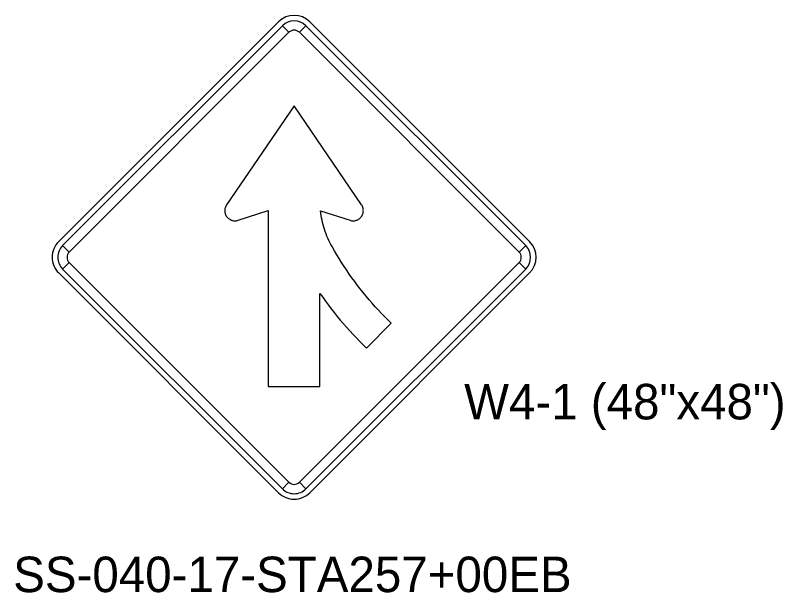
# Model space of a CAD drawing. Extents: x 620856.8 to 620948.6, y 415598.8 to 415658.2.
# Drawn here: x 620915.06 to 620923.7, y 415604 to 415610.5 of the extents above; entities that cross this region are included whole.
import ezdxf

# ---------------------------------------------------------------- set-up
doc = ezdxf.new("R2010")
doc.units = 0
doc.layers.add('SIGNS', color=7, linetype='Continuous')

msp = doc.modelspace()

# ---------------------------------------------------------------- linework, layer by layer
at = {"layer": 'SIGNS'}
for p, q in [((620918.0241, 415610.424), (620915.5492, 415607.9491)), ((620918.0683, 415610.3798), (620918.1419, 415610.3061)), ((620918.2598, 415610.3061), (620918.3334, 415610.3798)), ((620920.8525, 415607.9491), (620918.3776, 415610.424)), ((620917.4389, 415608.3624), (620917.4344, 415608.3546)), ((620917.5685, 415608.1889), (620917.908, 415608.298)), ((620917.908, 415608.298), (620917.908, 415606.3159)), ((620918.5006, 415608.2693), (620918.4974, 415608.2959)), ((620918.4974, 415608.2959), (620918.8304, 415608.1889)), ((620915.667, 415607.8312), (620915.5934, 415607.9049)), ((620920.8083, 415607.9049), (620920.7346, 415607.8312)), ((620915.5934, 415607.6397), (620915.667, 415607.7134)), ((620920.7346, 415607.7134), (620920.8083, 415607.6397)), ((620915.5492, 415607.5955), (620918.0241, 415605.1207)), ((620918.3776, 415605.1207), (620920.8525, 415607.5955)), ((620918.4908, 415606.3159), (620918.4908, 415607.3662)), ((620918.4908, 415607.3662), (620918.522, 415607.3219)), ((620919.0153, 415606.749), (620919.295, 415607.0287)), ((620917.908, 415606.3159), (620918.4908, 415606.3159)), ((620918.1419, 415605.2385), (620918.0683, 415605.1649)), ((620918.3334, 415605.1649), (620918.2598, 415605.2385))]:
    msp.add_line(p, q, dxfattribs=at)
for points in [[(620918.0683, 415610.3798), (620915.5934, 415607.9049), (620915.667, 415607.8312), (620918.1419, 415610.3061), (620918.0683, 415610.3798), (620918.0683, 415610.3798)], [(620920.8083, 415607.9049), (620918.3334, 415610.3798), (620918.2598, 415610.3061), (620920.7346, 415607.8312), (620920.8083, 415607.9049), (620920.8083, 415607.9049)], [(620915.5934, 415607.6397), (620918.0683, 415605.1649), (620918.1419, 415605.2385), (620915.667, 415607.7134), (620915.5934, 415607.6397), (620915.5934, 415607.6397)], [(620918.3334, 415605.1649), (620920.8083, 415607.6397), (620920.7346, 415607.7134), (620918.2598, 415605.2385), (620918.3334, 415605.1649), (620918.3334, 415605.1649)]]:
    msp.add_lwpolyline(points, close=True, dxfattribs=at)
for points in [[(620918.96, 415608.3624), (620918.1996, 415609.4787), (620917.4389, 415608.3624)], [(620917.4344, 415608.3546), (620917.4303, 415608.3468), (620917.4266, 415608.3386), (620917.4237, 415608.3304), (620917.4216, 415608.3218), (620917.42, 415608.3132), (620917.4192, 415608.3041), (620917.4192, 415608.2955), (620917.4196, 415608.2865), (620917.4208, 415608.2779), (620917.4229, 415608.2693), (620917.4253, 415608.2607), (620917.4286, 415608.2525), (620917.4323, 415608.2443), (620917.4368, 415608.2365), (620917.4417, 415608.2295), (620917.4475, 415608.2225), (620917.4536, 415608.216), (620917.4602, 415608.2102), (620917.4672, 415608.2045), (620917.4746, 415608.2), (620917.4823, 415608.1955), (620917.4905, 415608.1918), (620917.4987, 415608.1889), (620917.5074, 415608.1864), (620917.516, 415608.1848), (620917.5246, 415608.1836), (620917.5336, 415608.1836), (620917.5426, 415608.184), (620917.5512, 415608.1848), (620917.5599, 415608.1864), (620917.5685, 415608.1889)], [(620918.8304, 415608.1889), (620918.839, 415608.1864), (620918.8476, 415608.1848), (620918.8566, 415608.184), (620918.8656, 415608.1836), (620918.8742, 415608.1836), (620918.8833, 415608.1848), (620918.8919, 415608.1864), (620918.9005, 415608.1889), (620918.9087, 415608.1918), (620918.9169, 415608.1955), (620918.9247, 415608.2), (620918.9321, 415608.2045), (620918.939, 415608.2102), (620918.9456, 415608.216), (620918.9517, 415608.2225), (620918.9571, 415608.2295), (620918.9624, 415608.2365), (620918.9665, 415608.2443), (620918.9706, 415608.2525), (620918.9739, 415608.2607), (620918.9764, 415608.2693), (620918.978, 415608.2779), (620918.9792, 415608.2865), (620918.98, 415608.2955), (620918.9796, 415608.3041), (620918.9788, 415608.3132), (620918.9776, 415608.3218), (620918.9751, 415608.3304), (620918.9723, 415608.3386), (620918.969, 415608.3468), (620918.9649, 415608.3546), (620918.96, 415608.3624)], [(620918.6278, 415607.892), (620918.6146, 415607.9154), (620918.6027, 415607.9391), (620918.5909, 415607.9633), (620918.5802, 415607.9875), (620918.5695, 415608.0121), (620918.5601, 415608.0372), (620918.5507, 415608.0622), (620918.5425, 415608.0876), (620918.5343, 415608.113), (620918.5273, 415608.1385), (620918.5207, 415608.1643), (620918.5146, 415608.1905), (620918.5092, 415608.2168), (620918.5047, 415608.243), (620918.5006, 415608.2693)], [(620919.295, 415607.0287), (620919.2577, 415607.0652), (620919.2212, 415607.1021), (620919.1847, 415607.1394), (620919.149, 415607.1776), (620919.1137, 415607.2161), (620919.0789, 415607.2551), (620919.0448, 415607.2945), (620919.0112, 415607.3342), (620918.9784, 415607.3744), (620918.9456, 415607.4154), (620918.914, 415607.4565), (620918.8824, 415607.4983), (620918.8517, 415607.5405), (620918.8217, 415607.5832), (620918.7922, 415607.6258), (620918.7631, 415607.6693), (620918.7348, 415607.7132), (620918.7069, 415607.7575), (620918.6798, 415607.8018), (620918.6536, 415607.8469), (620918.6278, 415607.892)], [(620918.522, 415607.3219), (620918.5535, 415607.2781), (620918.5859, 415607.2346), (620918.6187, 415607.1915), (620918.6524, 415607.1493), (620918.686, 415607.107), (620918.7204, 415607.0652), (620918.7557, 415607.0242), (620918.7914, 415606.9836), (620918.8275, 415606.943), (620918.864, 415606.9032), (620918.9009, 415606.8643), (620918.9386, 415606.8253), (620918.9768, 415606.7867), (620919.0153, 415606.749)]]:
    msp.add_lwpolyline(points, dxfattribs=at)
for centre, radius, start, end in [((620918.2008, 415610.2472), 0.25, 45, 134.99975), ((620918.2008, 415610.2472), 0.1875, 45, 134.99975), ((620918.2008, 415610.2472), 0.0833, 45, 134.99975), ((620915.726, 415607.7723), 0.25, 134.99975, 224.99996), ((620915.726, 415607.7723), 0.1875, 134.99975, 224.99996), ((620920.6757, 415607.7723), 0.1875, 315.00017, 44.99981), ((620920.6757, 415607.7723), 0.25, 315.00017, 44.99981), ((620915.726, 415607.7723), 0.0833, 134.99975, 224.99996), ((620920.6757, 415607.7723), 0.0833, 315.00017, 44.99981), ((620918.2008, 415605.2974), 0.0833, 224.99996, 315.00017), ((620918.2008, 415605.2974), 0.25, 224.99996, 315.00017), ((620918.2008, 415605.2974), 0.1875, 224.99996, 315.00017)]:
    msp.add_arc(centre, radius, start, end, dxfattribs=at)

# ---------------------------------------------------------------- texts
for s, p in [('W4-1 (48"x48")', (620920.1151, 415605.9466)), ('SS-040-17-STA257+00EB', (620915.0366, 415604.0011))]:
    msp.add_text(s, height=0.4, rotation=0, dxfattribs=at).set_placement(p)

doc.saveas('drawing.dxf')
